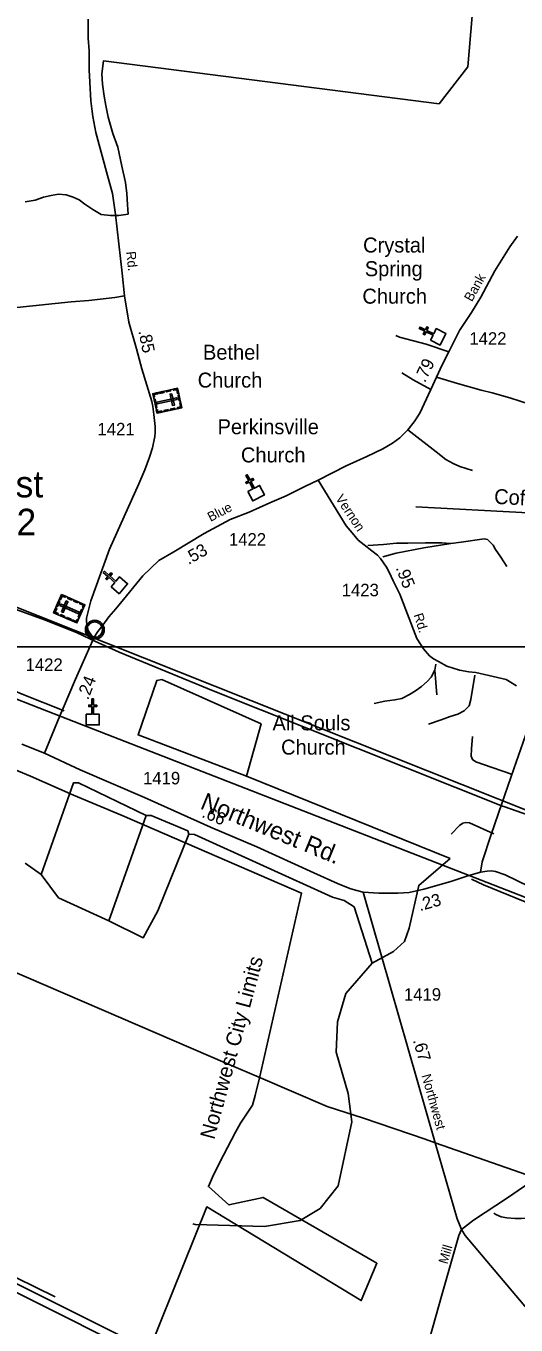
# Model space of a CAD drawing. Extents: x 2225501 to 2309677, y 165449 to 227696.
# Drawn here: x 2253045 to 2257951, y 199877 to 212881 of the extents above; entities that cross this region are included whole.
import ezdxf

# ---------------------------------------------------------------- set-up
doc = ezdxf.new("R2010")
doc.units = 0
for name, color, linetype in [('Black Area Fill Shapes', 7, 'Continuous'), ('E_RDY_CMT_EOP', 7, 'Continuous'), ('MARK ENDS WORD SYMBOL CELL', 7, 'Continuous'), ('Old_Level_3', 7, 'Continuous'), ('Old_Level_33', 7, 'Continuous'), ('Old_Level_41', 7, 'Continuous'), ('P_HYD_Diversion_Ditch_Label', 7, 'Continuous'), ('P_HYD_Drop_Inlet_Box_Type_A_48_Dia-Bottom_CELL', 7, 'Continuous'), ('P_HYD_Drop_Inlet_Grate_2_Narrow_Slot_and_Flat_Grates_840_29_54_Dia_CELL', 7, 'Continuous'), ('P_HYD_Endwall_838_01_48_Dia_Single_CELL', 7, 'Continuous'), ('P_HYD_RipRap_Pad_876_02_36in_Outlet_With_Ditch-Top_CELL', 7, 'Continuous'), ('P_HYD_Typical_Terminator_CELL', 7, 'Continuous'), ('P_RDY_Dimension_Text', 7, 'Continuous'), ('Prop Mkg Solid Yellow Edge Line', 7, 'Continuous'), ('Prop Support', 7, 'Continuous'), ('Scratch_Level_1', 7, 'Continuous'), ('Scratch_Level_5', 7, 'Continuous'), ('Typical Terminator CELL', 7, 'Continuous')]:
    doc.layers.add(name, color=color, linetype=linetype)

msp = doc.modelspace()

# ---------------------------------------------------------------- linework, layer by layer
at = {"layer": 'Black Area Fill Shapes'}
msp.add_line((2253690, 206744), (2253736, 206723), dxfattribs=at)
for points in [[(2252457, 207211), (2252551, 207176), (2252874, 207066), (2253229, 206937), (2253552, 206808), (2253690, 206744)], [(2244873, 206904), (2245139, 206787), (2246596, 206147), (2247912, 205580), (2249459, 204911), (2251132, 204181), (2252661, 203526), (2253801, 203037), (2255064, 202492), (2255394, 202351)], [(2253736, 206723), (2253979, 206611), (2254918, 206225), (2257817, 205072)], [(2257817, 205072), (2257828, 205067), (2258085, 204976), (2258478, 204825), (2258739, 204751), (2259175, 204643), (2259682, 204519), (2259831, 204444), (2260234, 204242)], [(2255394, 202351), (2256061, 202066), (2256424, 201947), (2257040, 201738), (2257142, 201702)], [(2257142, 201702), (2257926, 201426), (2258182, 201337)], [(2254290, 199621), (2252915, 200311), (2250920, 201309), (2250846, 201345)], [(2250806, 201279), (2252944, 200206), (2254261, 199546)]]:
    msp.add_lwpolyline(points, dxfattribs=at)
at = {"layer": 'Old_Level_3'}
for p, q in [((2257147, 206491), (2257138, 206433)), ((2257138, 206433), (2257159, 206184)), ((2253336, 200159), (2250865, 201378))]:
    msp.add_line(p, q, dxfattribs=at)
for points in [[(2254032, 210181), (2253934, 210164), (2253673, 210134), (2253497, 210118), (2252566, 210021), (2252480, 210016), (2252308, 210000), (2252195, 209969), (2252109, 209951), (2251987, 209916), (2251879, 209891), (2251760, 209850), (2251670, 209815), (2251561, 209760)], [(2257277, 209619), (2257053, 209695), (2256786, 209765), (2256748, 209781)], [(2257099, 209242), (2256921, 209340), (2256807, 209410)], [(2257154, 209366), (2257364, 209302), (2257603, 209236), (2257712, 209207), (2257889, 209157), (2258097, 209092), (2258199, 209056), (2258272, 209027)], [(2256869, 208837), (2257152, 208619), (2257250, 208540), (2257321, 208502), (2257389, 208471), (2257515, 208432)], [(2256466, 207681), (2256624, 207690), (2256753, 207702), (2256869, 207704), (2257044, 207707), (2257210, 207707), (2257299, 207699)], [(2256616, 207567), (2256750, 207602), (2257029, 207658), (2257299, 207699)], [(2257299, 207699), (2257403, 207715), (2257631, 207747), (2257665, 207739), (2257721, 207684), (2257747, 207640), (2257800, 207564), (2257859, 207469)], [(2253426, 206025), (2253023, 206186), (2252520, 206396), (2252492, 206401), (2252455, 206433), (2252409, 206507), (2252406, 206547), (2252420, 206633), (2252421, 206665), (2252445, 206727), (2252453, 206759), (2252464, 206787), (2252478, 206841), (2252472, 206857), (2252476, 206879), (2252432, 207073), (2252436, 207103), (2252434, 207129), (2252457, 207211)], [(2257138, 206433), (2257100, 206361), (2257061, 206319), (2257005, 206268), (2256945, 206224), (2256884, 206189), (2256808, 206149), (2256738, 206134), (2256638, 206123), (2256532, 206100)], [(2257540, 206381), (2257500, 206138), (2257482, 206074), (2257433, 206024), (2257367, 205991), (2257293, 205969), (2257200, 205934), (2257076, 205893)], [(2257516, 205767), (2257506, 205646), (2257502, 205571), (2257516, 205538), (2257548, 205515), (2257712, 205459), (2257917, 205387)], [(2257729, 204793), (2257486, 204905), (2257448, 204907), (2257420, 204902), (2257386, 204878), (2257303, 204791)], [(2259947, 202618), (2259881, 202711), (2259798, 202796), (2259410, 203099), (2259319, 203148), (2259111, 203245), (2258860, 203345), (2258828, 203364), (2258630, 203625), (2258559, 203704), (2258489, 203773), (2258466, 203799), (2258442, 203845), (2258375, 203952), (2258351, 203976), (2258275, 204016), (2258205, 204047), (2257627, 204284), (2257504, 204339)], [(2258275, 200977), (2258064, 200947), (2258004, 200943), (2257944, 200942), (2257860, 200951), (2257804, 200961), (2257748, 200984), (2257728, 200996)]]:
    msp.add_lwpolyline(points, dxfattribs=at)
at = {"layer": 'Old_Level_33'}
msp.add_line((2253384, 205974), (2253232, 205601), dxfattribs=at)
for points in [[(2253728, 206762), (2253704, 206777), (2253666, 206829), (2253661, 206861), (2253651, 206917), (2253652, 206954), (2253666, 207021), (2253696, 207127), (2253880, 207644), (2254175, 208298), (2254234, 208438), (2254282, 208563), (2254312, 208658), (2254334, 208773), (2254337, 208811), (2254337, 208871), (2254326, 208992), (2254315, 209071), (2254305, 209121), (2254204, 209450), (2254151, 209648), (2254075, 209915), (2254032, 210180), (2254009, 210407), (2253940, 210992), (2253929, 211086), (2253910, 211203), (2253879, 211324), (2253862, 211385), (2253744, 211815), (2253714, 211973), (2253703, 212050), (2253693, 212132), (2253683, 212317), (2253678, 212441), (2253676, 212633), (2253669, 212758), (2253669, 212759), (2253668, 212862), (2253668, 212949)], [(2257967, 210775), (2257888, 210670), (2257738, 210429), (2257598, 210167), (2257506, 210014), (2257385, 209833), (2257277, 209619), (2257212, 209489), (2257154, 209366), (2257099, 209242), (2256989, 209006), (2256933, 208917), (2256869, 208837), (2256787, 208757), (2256713, 208705), (2256619, 208648), (2256456, 208571), (2256251, 208477), (2255970, 208333)], [(2255970, 208333), (2255837, 208270), (2255649, 208179), (2255487, 208108), (2255278, 208013), (2255090, 207939), (2254830, 207800), (2254524, 207618), (2254376, 207529), (2254216, 207376), (2253993, 207104), (2253944, 207046), (2253876, 206965), (2253813, 206884), (2253763, 206821), (2253728, 206762)], [(2257955, 206274), (2257853, 206338), (2257680, 206379), (2257548, 206408), (2257479, 206416), (2257384, 206433), (2257257, 206473), (2257174, 206518), (2257125, 206547), (2257085, 206577), (2257026, 206645), (2256958, 206749), (2256789, 207193), (2256721, 207327), (2256682, 207412), (2256654, 207465), (2256595, 207549), (2256563, 207583), (2256507, 207628), (2256432, 207688), (2256372, 207735), (2256309, 207808), (2256250, 207878), (2255970, 208333)], [(2253728, 206762), (2253540, 206342), (2253419, 206053), (2253384, 205974)], [(2257596, 204412), (2257613, 204513), (2257701, 204788), (2257808, 205099), (2257929, 205446), (2258069, 205844)], [(2253232, 205601), (2253005, 205692)], [(2256422, 204211), (2256344, 204230), (2256287, 204248), (2256164, 204297), (2255927, 204402), (2255357, 204664), (2254891, 204860), (2254231, 205158), (2253589, 205435), (2253232, 205601)], [(2256422, 204211), (2256578, 204201), (2256767, 204201), (2256880, 204208), (2257027, 204239), (2257297, 204316), (2257467, 204374), (2257596, 204412)], [(2257596, 204412), (2257662, 204419), (2257704, 204423), (2257747, 204418), (2257842, 204383), (2258205, 204207)], [(2257406, 200835), (2257385, 200884), (2257361, 200939), (2257142, 201702), (2256422, 204211)], [(2260763, 203008), (2260671, 203041), (2260642, 203045), (2260612, 203040), (2260558, 203015), (2259947, 202618), (2259719, 202494), (2259313, 202263), (2259005, 202071), (2258952, 202027), (2258879, 201959), (2258751, 201809), (2258663, 201710), (2258560, 201618), (2258144, 201341), (2257867, 201150), (2257526, 200928), (2257406, 200835)], [(2257406, 200835), (2257377, 200772), (2257212, 200191), (2256987, 199396), (2256960, 199295), (2256938, 199183), (2256927, 199075), (2256939, 198675), (2256934, 198381), (2256936, 198162), (2256952, 197292), (2256950, 196947), (2256952, 196843), (2256957, 196790)], [(2260177, 196311), (2260246, 196457), (2260249, 196467), (2260283, 196565), (2260294, 196619), (2260313, 196715), (2260321, 196771), (2260328, 196869), (2260321, 196979), (2260313, 197083), (2260289, 197201), (2260250, 197307), (2260204, 197416), (2260102, 197588), (2259969, 197740), (2259181, 198716), (2257442, 200774), (2257406, 200835)]]:
    msp.add_lwpolyline(points, dxfattribs=at)
at = {"layer": 'Old_Level_41'}
msp.add_line((2253403, 205966), (2257541, 204355), dxfattribs=at)
for points in [[(2246607, 208618), (2246834, 208530), (2247936, 208099), (2248412, 207914), (2252617, 206273), (2253403, 205966)], [(2257541, 204355), (2261853, 202675), (2263431, 202061), (2263685, 201962), (2264357, 201700), (2265036, 201436), (2265586, 201218), (2266169, 200989), (2266778, 200746), (2267396, 200499), (2268070, 200237)]]:
    msp.add_lwpolyline(points, dxfattribs=at)
at = {"layer": 'P_HYD_Diversion_Ditch_Label'}
msp.add_lwpolyline([(2253656, 206850), (2253657, 206855), (2253659, 206862), (2253662, 206869), (2253665, 206875), (2253668, 206881), (2253672, 206886), (2253676, 206890), (2253680, 206895), (2253686, 206899), (2253691, 206903), (2253696, 206906), (2253701, 206908), (2253707, 206910), (2253712, 206912), (2253717, 206913), (2253721, 206914), (2253726, 206915), (2253732, 206915), (2253736, 206915), (2253742, 206915), (2253747, 206914), (2253752, 206913), (2253757, 206912), (2253762, 206910), (2253769, 206907), (2253775, 206903), (2253780, 206900), (2253785, 206896), (2253789, 206893), (2253793, 206888), (2253796, 206884), (2253800, 206879), (2253803, 206874), (2253805, 206869), (2253807, 206864), (2253809, 206859), (2253810, 206854), (2253811, 206848), (2253812, 206843), (2253812, 206837), (2253812, 206832), (2253811, 206826), (2253810, 206820), (2253809, 206814), (2253807, 206808), (2253805, 206803), (2253801, 206797), (2253798, 206792), (2253795, 206787), (2253790, 206783), (2253785, 206778), (2253780, 206774), (2253775, 206770), (2253771, 206768), (2253764, 206764), (2253757, 206762), (2253751, 206760), (2253744, 206759), (2253740, 206758), (2253735, 206758), (2253730, 206758), (2253725, 206759), (2253720, 206759), (2253714, 206761), (2253709, 206762), (2253704, 206764), (2253700, 206766), (2253696, 206768), (2253689, 206772), (2253683, 206776), (2253678, 206781), (2253674, 206786), (2253671, 206790), (2253668, 206794), (2253664, 206801), (2253662, 206805), (2253660, 206809), (2253658, 206817), (2253656, 206824), (2253655, 206829), (2253655, 206835), (2253655, 206840), (2253656, 206846)], close=True, dxfattribs=at)
for centre, radius in [((2253734, 206837), 94.3), ((2253733, 206838), 76.7)]:
    msp.add_circle(centre, radius, dxfattribs=at)
at = {"layer": 'P_HYD_Endwall_838_01_48_Dia_Single_CELL'}
for points in [[(2253037, 211121), (2253136, 211136), (2253219, 211167), (2253298, 211183), (2253370, 211196), (2253446, 211189), (2253518, 211168), (2253576, 211140), (2253633, 211097), (2253714, 211042), (2253798, 210995), (2253890, 210983), (2253975, 210985), (2254067, 210998), (2254062, 211089), (2254055, 211204), (2254042, 211313), (2254005, 211476), (2253963, 211669), (2253915, 211804), (2253868, 211967), (2253843, 212083), (2253828, 212178), (2253812, 212297), (2253803, 212403), (2253820, 212531), (2257180, 212100), (2257467, 212472), (2257673, 214871)], [(2254046, 199046), (2254854, 201059), (2256402, 200122), (2256559, 200496), (2255419, 201155), (2255076, 201080), (2254872, 201263), (2254924, 201380), (2255021, 201579), (2255142, 201809), (2255192, 201898), (2255314, 202079), (2255338, 202174), (2255386, 202365), (2255804, 204201), (2254008, 204976), (2253522, 205182), (2253091, 205370), (2252784, 205498)]]:
    msp.add_lwpolyline(points, dxfattribs=at)
at = {"layer": 'P_HYD_RipRap_Pad_876_02_36in_Outlet_With_Ditch-Top_CELL'}
for points in [[(2253037, 211121), (2253136, 211136), (2253219, 211167), (2253298, 211183), (2253370, 211196), (2253446, 211189), (2253518, 211168), (2253576, 211140), (2253633, 211097), (2253714, 211042), (2253798, 210995), (2253890, 210983), (2253975, 210985), (2254067, 210998), (2254062, 211089), (2254055, 211204), (2254042, 211313), (2254005, 211476), (2253963, 211669), (2253915, 211804), (2253868, 211967), (2253843, 212083), (2253828, 212178), (2253812, 212297), (2253803, 212403), (2253820, 212531), (2257180, 212100), (2257467, 212472), (2257673, 214871)], [(2254046, 199046), (2254854, 201059), (2256402, 200122), (2256559, 200496), (2255419, 201155), (2255076, 201080), (2254872, 201263), (2254924, 201380), (2255021, 201579), (2255142, 201809), (2255192, 201898), (2255314, 202079), (2255338, 202174), (2255386, 202365), (2255804, 204201), (2254008, 204976), (2253522, 205182), (2253091, 205370), (2252784, 205498)]]:
    msp.add_lwpolyline(points, dxfattribs=at)
at = {"layer": 'P_HYD_Typical_Terminator_CELL'}
msp.add_line((2244657, 206666), (2298327, 206666), dxfattribs=at)
at = {"layer": 'Prop Mkg Solid Yellow Edge Line'}
for points in [[(2254563, 209254), (2254606, 209059), (2254357, 209005), (2254314, 209200)], [(2254383, 209215), (2254425, 209224), (2254428, 209213), (2254385, 209203)], [(2254448, 209229), (2254491, 209238), (2254493, 209227), (2254451, 209218)], [(2254521, 209245), (2254523, 209234), (2254555, 209240), (2254563, 209201), (2254574, 209203), (2254563, 209254)], [(2254322, 209167), (2254333, 209170), (2254328, 209191), (2254368, 209200), (2254365, 209211), (2254315, 209200)], [(2254338, 209146), (2254356, 209063), (2254345, 209061), (2254327, 209144)], [(2254558, 209141), (2254554, 209159), (2254356, 209116), (2254360, 209098)], [(2254505, 209200), (2254487, 209196), (2254512, 209081), (2254531, 209084)], [(2254563, 209050), (2254561, 209061), (2254592, 209068), (2254584, 209108), (2254595, 209110), (2254606, 209059)], [(2254579, 209182), (2254590, 209131), (2254579, 209128), (2254568, 209179)], [(2254350, 209038), (2254361, 209040), (2254366, 209018), (2254405, 209027), (2254408, 209016), (2254357, 209005)], [(2254425, 209032), (2254467, 209041), (2254470, 209030), (2254427, 209021)], [(2254489, 209046), (2254532, 209055), (2254534, 209044), (2254492, 209035)], [(2253322, 207007), (2253401, 207189), (2253635, 207088), (2253555, 206905)], [(2253441, 207172), (2253437, 207162), (2253407, 207174), (2253391, 207137), (2253381, 207142), (2253401, 207189)], [(2253504, 207132), (2253464, 207150), (2253468, 207160), (2253508, 207143)], [(2253362, 206989), (2253366, 207000), (2253337, 207013), (2253353, 207050), (2253343, 207054), (2253322, 207007)], [(2253351, 207075), (2253372, 207122), (2253383, 207118), (2253362, 207070)], [(2253392, 207095), (2253385, 207078), (2253571, 206997), (2253578, 207014)], [(2253401, 207017), (2253418, 207010), (2253465, 207118), (2253448, 207125)], [(2253564, 207106), (2253524, 207123), (2253529, 207134), (2253569, 207117)], [(2253568, 206962), (2253602, 207040), (2253612, 207036), (2253578, 206958)], [(2253622, 207057), (2253611, 207062), (2253620, 207082), (2253583, 207098), (2253587, 207108), (2253635, 207088)], [(2253430, 206960), (2253390, 206977), (2253394, 206988), (2253434, 206970)], [(2253491, 206933), (2253451, 206950), (2253456, 206961), (2253496, 206943)], [(2253569, 206935), (2253558, 206940), (2253549, 206920), (2253512, 206936), (2253508, 206926), (2253555, 206905)]]:
    msp.add_lwpolyline(points, close=True, dxfattribs=at)
at = {"layer": 'Prop Support'}
for p, q in [((2257293, 204546), (2255254, 205370)), ((2253874, 203924), (2254249, 204979)), ((2253196, 204386), (2253037, 204501))]:
    msp.add_line(p, q, dxfattribs=at)
for points in [[(2259717, 204515), (2259333, 204654), (2258473, 204864), (2251395, 207679)], [(2255254, 205370), (2255399, 205895), (2254404, 206338), (2254354, 206329), (2254167, 205785), (2255254, 205370)], [(2253196, 204386), (2253521, 205305), (2253571, 205304), (2254249, 204979)], [(2254675, 204791), (2254667, 204824), (2254299, 204978), (2254249, 204979)], [(2253874, 203924), (2254217, 203753), (2254365, 204023), (2254675, 204791)], [(2256510, 203499), (2256330, 204063), (2256230, 204127), (2256113, 204159), (2254733, 204789), (2254675, 204791)], [(2256510, 203499), (2256725, 203616), (2256833, 203715), (2256882, 203849), (2256978, 204277), (2257293, 204546)], [(2253874, 203924), (2253372, 204153), (2253196, 204386)], [(2256510, 203499), (2256246, 203195), (2256165, 202912), (2256151, 202610), (2256271, 202194), (2256306, 201912), (2256170, 201271), (2255989, 201045), (2255789, 200925), (2255432, 200863), (2254740, 200883), (2254717, 200890)]]:
    msp.add_lwpolyline(points, dxfattribs=at)
at = {"layer": 'Scratch_Level_5'}
for points in [[(2257095, 209734), (2257120, 209785), (2257051, 209818), (2257037, 209789), (2257023, 209796), (2257037, 209825), (2256983, 209852), (2256990, 209866), (2257044, 209840), (2257058, 209868), (2257073, 209861), (2257059, 209833), (2257127, 209799), (2257152, 209851), (2257248, 209804), (2257191, 209687)], [(2255267, 208221), (2255317, 208247), (2255282, 208314), (2255254, 208300), (2255246, 208314), (2255275, 208329), (2255247, 208382), (2255261, 208389), (2255289, 208336), (2255317, 208351), (2255325, 208337), (2255296, 208322), (2255332, 208254), (2255383, 208281), (2255432, 208186), (2255316, 208126)], [(2253897, 207268), (2253934, 207311), (2253877, 207361), (2253856, 207337), (2253844, 207347), (2253865, 207371), (2253819, 207411), (2253830, 207423), (2253875, 207384), (2253896, 207408), (2253908, 207397), (2253887, 207373), (2253945, 207323), (2253982, 207367), (2254063, 207297), (2253977, 207198)], [(2253649, 205991), (2253706, 205991), (2253706, 206067), (2253674, 206067), (2253674, 206083), (2253706, 206083), (2253706, 206144), (2253722, 206144), (2253722, 206083), (2253754, 206083), (2253754, 206067), (2253722, 206067), (2253722, 205991), (2253779, 205991), (2253779, 205885), (2253649, 205885)]]:
    msp.add_lwpolyline(points, close=True, dxfattribs=at)
at = {"layer": 'Typical Terminator CELL'}
msp.add_lwpolyline([(2256948, 208066), (2258072, 208008), (2258406, 208018), (2258755, 208129), (2260103, 208217), (2260319, 208292), (2260875, 208632), (2260949, 208647)], dxfattribs=at)

# ---------------------------------------------------------------- texts
at = {"layer": 'E_RDY_CMT_EOP'}
for s, p in [('1422', (2257484, 209690)), ('1421', (2253761, 208783)), ('1422', (2255077, 207679)), ('1423', (2256206, 207172)), ('1422', (2253041, 206425)), ('1419', (2254217, 205289)), ('1419', (2256829, 203124))]:
    msp.add_text(s, height=125, dxfattribs=at).set_placement(p)
at = {"layer": 'MARK ENDS WORD SYMBOL CELL'}
for s, height, rotation, p in [('Rd.', 95, 276.2859, (2254048, 210620)), ('Bank', 95, 60.7996, (2257509, 210114)), ('Vernon', 95, 303.7451, (2256139, 208152)), ('Blue', 95, 27.4989, (2254893, 207916)), ('Rd.', 95, 287.3911, (2256925, 206986)), ('Northwest Rd.', 175, 337.6753, (2254780, 205050)), ('Northwest', 95, 285.6854, (2257004, 202375)), ('Mill', 95, 73.7046, (2257263, 200481))]:
    msp.add_text(s, height=height, rotation=rotation, dxfattribs=at).set_placement(p)
at = {"layer": 'P_HYD_Drop_Inlet_Box_Type_A_48_Dia-Bottom_CELL'}
for s, p in [('Northwest', (2251622, 208162)), ('Pop. 752', (2251729, 207783))]:
    msp.add_text(s, height=265, dxfattribs=at).set_placement(p)
msp.add_text('Northwest City Limits', height=150, rotation=74.8701, dxfattribs=at).set_placement((2254930, 201727))
at = {"layer": 'P_HYD_Drop_Inlet_Grate_2_Narrow_Slot_and_Flat_Grates_840_29_54_Dia_CELL'}
for s, p in [('Crystal', (2256420, 210613)), ('Spring', (2256437, 210376)), ('Church', (2256413, 210101)), ('Bethel', (2254817, 209540)), ('Church', (2254764, 209261)), ('Perkinsville', (2254963, 208794)), ('Church', (2255197, 208512)), ('All Souls', (2255513, 205830)), ('Church', (2255599, 205587))]:
    msp.add_text(s, height=150, dxfattribs=at).set_placement(p)
at = {"layer": 'P_RDY_Dimension_Text'}
for s, rotation, p in [('.85', 281.3123, (2254170, 209826)), ('.79', 63.9183, (2257039, 209303)), ('.53', 29.2313, (2254672, 207485)), ('.95', 290.8762, (2256745, 207456)), ('.24', 68.8484, (2253667, 206128)), ('.66', 337.2258, (2254797, 204965)), ('.23', 15.771, (2256989, 204019)), ('.67', 286.0095, (2256918, 202727))]:
    msp.add_text(s, height=125, rotation=rotation, dxfattribs=at).set_placement(p)
at = {"layer": 'Scratch_Level_1'}
msp.add_text('Coffin', height=150, rotation=357.0462, dxfattribs=at).set_placement((2257729, 208098))

doc.saveas('drawing.dxf')
